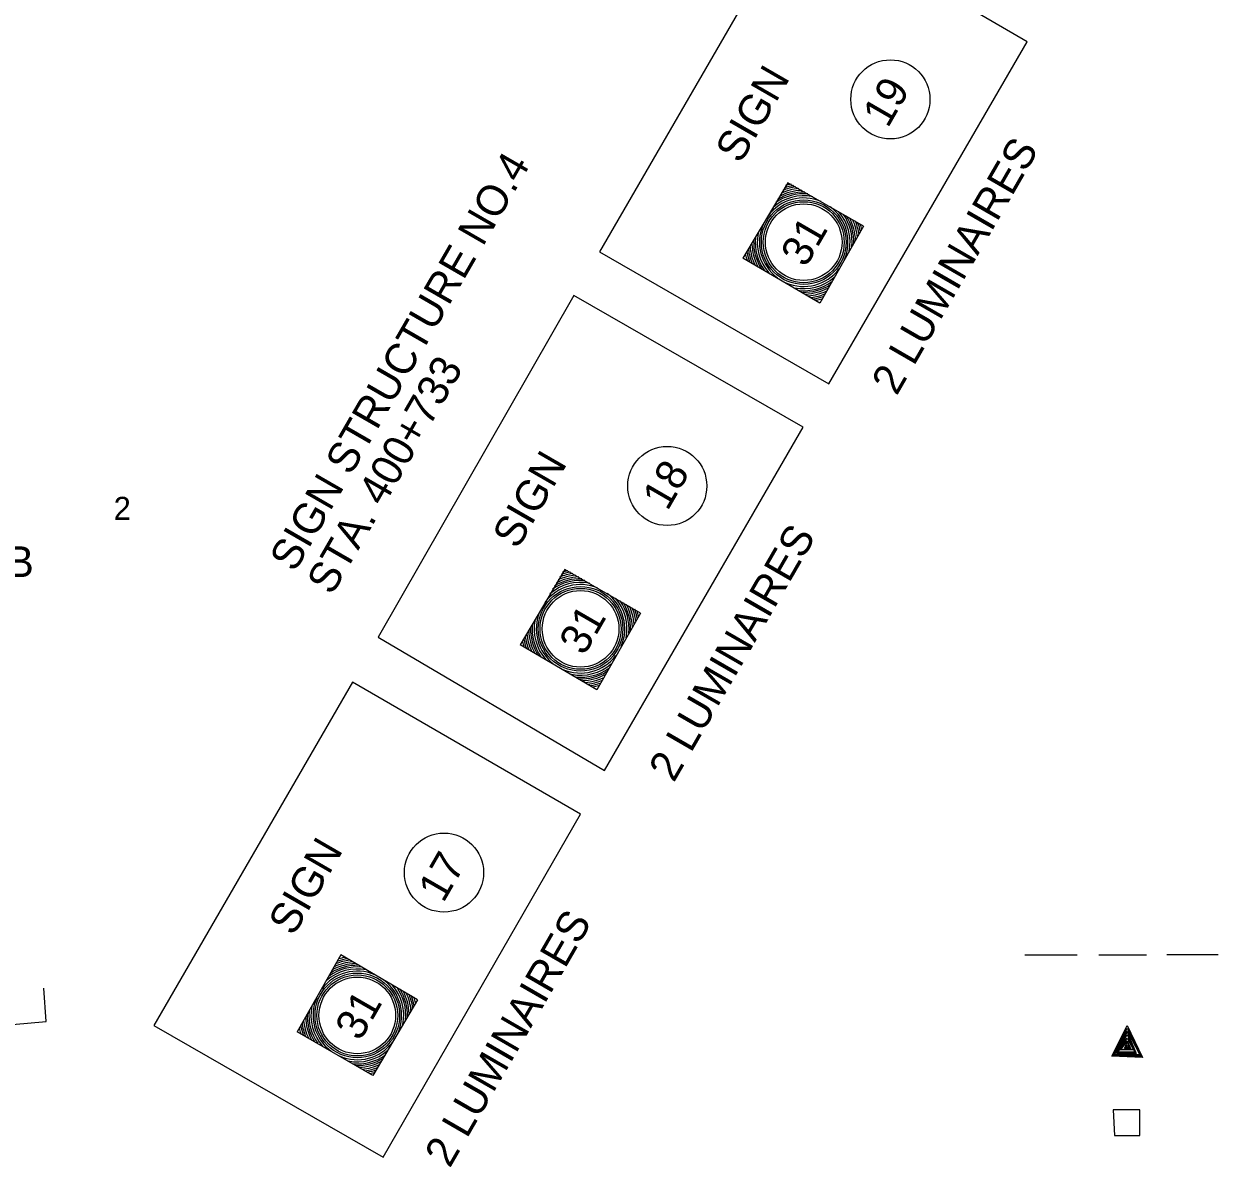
# Model space of a CAD drawing. Extents: x 36 to 2622, y -5330 to 219.
# Drawn here: x 2300.3 to 2416.9, y -4454.9 to -4343.3 of the extents above; entities that cross this region are included whole.
import ezdxf

# ---------------------------------------------------------------- set-up
doc = ezdxf.new("R2010")
doc.units = 0
doc.layers.add('2', color=7, linetype='Continuous')

msp = doc.modelspace()

# ---------------------------------------------------------------- linework, layer by layer
at = {"layer": '2'}
for p, q in [((2397.98, -4434.2), (2403.11, -4434.2)), ((2405.23, -4434.2), (2409.86, -4434.2)), ((2416.86, -4434.2), (2411.86, -4434.2)), ((2302.48, -4440.7), (2302.23, -4437.45)), ((2287.23, -4442.08), (2302.48, -4440.7)), ((2406.48, -4444.08), (2407.98, -4441.08)), ((2406.61, -4444.08), (2407.98, -4441.33)), ((2406.73, -4443.95), (2407.98, -4441.58)), ((2406.98, -4443.83), (2407.98, -4441.7)), ((2407.11, -4443.7), (2407.98, -4441.95)), ((2407.98, -4441.08), (2409.48, -4444.2)), ((2407.98, -4441.33), (2409.36, -4444.08)), ((2407.98, -4441.58), (2409.23, -4443.95)), ((2407.98, -4441.7), (2408.86, -4443.83)), ((2407.98, -4441.95), (2408.73, -4443.7)), ((2407.23, -4443.45), (2407.98, -4442.33)), ((2407.36, -4443.45), (2407.98, -4442.58)), ((2407.73, -4443.33), (2407.98, -4442.7)), ((2407.86, -4443.2), (2407.98, -4442.95)), ((2408.11, -4443.2), (2407.86, -4443.2)), ((2407.98, -4442.33), (2408.61, -4443.45)), ((2407.98, -4442.58), (2408.36, -4443.45)), ((2407.98, -4442.7), (2408.23, -4443.33)), ((2407.98, -4442.95), (2408.11, -4443.2)), ((2409.48, -4444.2), (2406.48, -4444.08)), ((2409.36, -4444.08), (2406.61, -4444.08)), ((2409.23, -4443.95), (2406.73, -4443.95)), ((2408.86, -4443.83), (2406.98, -4443.83)), ((2408.73, -4443.7), (2407.11, -4443.7)), ((2408.61, -4443.45), (2407.23, -4443.45)), ((2408.36, -4443.45), (2407.36, -4443.45)), ((2408.23, -4443.33), (2407.73, -4443.33))]:
    msp.add_line(p, q, dxfattribs=at)
for points in [[(2378.86, -4378.45), (2398.23, -4345.08), (2375.86, -4332.08), (2356.48, -4365.58)], [(2356.98, -4416.2), (2376.36, -4382.7), (2353.98, -4369.83), (2334.86, -4403.2)], [(2335.36, -4453.95), (2354.61, -4420.45), (2332.36, -4407.58), (2312.98, -4441.08)], [(2406.73, -4451.83), (2409.23, -4451.83), (2409.23, -4449.33), (2406.61, -4449.33)]]:
    msp.add_lwpolyline(points, close=True, dxfattribs=at)
for points in [[(2374.86, -4358.83), (2370.48, -4366.2)], [(2382.23, -4363.08), (2374.86, -4358.83)], [(2382.23, -4363.08), (2377.98, -4370.58)], [(2377.98, -4370.58), (2370.48, -4366.2)], [(2353.11, -4396.58), (2348.73, -4403.95)], [(2360.48, -4400.83), (2353.11, -4396.58)], [(2360.48, -4400.83), (2356.23, -4408.33)], [(2356.23, -4408.33), (2348.73, -4403.95)], [(2331.23, -4434.2), (2326.98, -4441.7)], [(2338.73, -4438.58), (2331.23, -4434.2)], [(2338.73, -4438.58), (2334.36, -4445.95)], [(2334.36, -4445.95), (2326.98, -4441.7)]]:
    msp.add_lwpolyline(points, dxfattribs=at)
for centre, radius in [((2384.87, -4350.7), 3.86), ((2376.41, -4364.64), 4.13), ((2376.41, -4364.64), 3.95), ((2376.41, -4364.64), 3.74), ((2363.09, -4388.43), 3.86), ((2354.63, -4402.37), 4.13), ((2354.63, -4402.37), 3.95), ((2354.63, -4402.37), 3.74), ((2341.3, -4426.16), 3.86), ((2332.84, -4440.1), 4.13), ((2332.84, -4440.1), 3.95), ((2332.84, -4440.1), 3.74)]:
    msp.add_circle(centre, radius, dxfattribs=at)
for centre, radius, start, end in [((2376.41, -4364.64), 5.45, 98.0414, 112.0368), ((2376.41, -4364.64), 5.62, 100.231, 109.8414), ((2376.41, -4364.64), 5.8, 102.2801, 107.7872), ((2376.41, -4364.64), 4.32, 66.9038, 143.621), ((2376.41, -4364.64), 4.53, 78.7747, 131.406), ((2376.41, -4364.64), 4.73, 84.969, 125.1626), ((2376.41, -4364.64), 4.89, 88.6036, 121.5088), ((2376.41, -4364.64), 5.06, 92.1022, 117.9954), ((2376.41, -4364.64), 5.26, 95.3377, 114.7487), ((2376.41, -4364.64), 4.32, 336.9038, 53.0962), ((2376.41, -4364.64), 4.53, 348.7747, 41.2253), ((2376.41, -4364.64), 4.73, 354.969, 35.031), ((2376.41, -4364.64), 4.89, 358.6036, 31.3964), ((2376.41, -4364.64), 5.06, 2.1022, 27.8978), ((2376.41, -4364.64), 5.26, 5.3377, 24.6623), ((2376.41, -4364.64), 5.45, 8.0414, 21.9586), ((2376.41, -4364.64), 5.62, 10.231, 19.769), ((2376.41, -4364.64), 4.53, 168.594, 221.406), ((2376.41, -4364.64), 4.32, 156.379, 233.621), ((2376.41, -4364.64), 5.8, 12.2801, 17.7199), ((2376.41, -4364.64), 5.26, 185.2513, 204.7486), ((2376.41, -4364.64), 5.06, 182.0046, 207.9954), ((2376.41, -4364.64), 4.89, 178.4912, 211.5088), ((2376.41, -4364.64), 4.73, 174.8374, 215.1626), ((2376.41, -4364.64), 5.8, 192.2128, 197.7872), ((2376.41, -4364.64), 5.62, 190.1586, 199.8414), ((2376.41, -4364.64), 5.45, 187.9632, 202.0368), ((2376.41, -4364.64), 4.32, 246.379, 323.0962), ((2376.41, -4364.64), 4.53, 258.594, 311.2253), ((2376.41, -4364.64), 4.73, 264.8374, 305.031), ((2376.41, -4364.64), 4.89, 268.4912, 301.3964), ((2376.41, -4364.64), 5.06, 272.0046, 297.8978), ((2376.41, -4364.64), 5.26, 275.2513, 294.6623), ((2376.41, -4364.64), 5.45, 277.9632, 291.9586), ((2376.41, -4364.64), 5.62, 280.1586, 289.769), ((2376.41, -4364.64), 5.8, 282.2128, 287.7199), ((2354.63, -4402.37), 4.73, 84.969, 125.1626), ((2354.63, -4402.37), 4.89, 88.6036, 121.5088), ((2354.63, -4402.37), 5.06, 92.1022, 117.9954), ((2354.63, -4402.37), 5.26, 95.3377, 114.7487), ((2354.63, -4402.37), 5.45, 98.0414, 112.0368), ((2354.63, -4402.37), 5.62, 100.231, 109.8414), ((2354.63, -4402.37), 5.8, 102.2801, 107.7872), ((2354.63, -4402.37), 4.32, 66.9038, 143.621), ((2354.63, -4402.37), 4.53, 78.7747, 131.406), ((2354.63, -4402.37), 4.32, 336.9038, 53.0962), ((2354.63, -4402.37), 4.53, 348.7747, 41.2253), ((2354.63, -4402.37), 4.73, 354.969, 35.031), ((2354.63, -4402.37), 4.89, 358.6036, 31.3964), ((2354.63, -4402.37), 5.06, 2.1022, 27.8978), ((2354.63, -4402.37), 4.32, 156.379, 233.621), ((2354.63, -4402.37), 5.26, 5.3377, 24.6623), ((2354.63, -4402.37), 5.45, 8.0414, 21.9586), ((2354.63, -4402.37), 5.62, 10.231, 19.769), ((2354.63, -4402.37), 5.8, 12.2801, 17.7199), ((2354.63, -4402.37), 4.89, 178.4912, 211.5088), ((2354.63, -4402.37), 4.73, 174.8374, 215.1626), ((2354.63, -4402.37), 4.53, 168.594, 221.406), ((2354.63, -4402.37), 5.8, 192.2128, 197.7872), ((2354.63, -4402.37), 5.62, 190.1586, 199.8414), ((2354.63, -4402.37), 5.45, 187.9632, 202.0368), ((2354.63, -4402.37), 5.26, 185.2513, 204.7486), ((2354.63, -4402.37), 5.06, 182.0046, 207.9954), ((2354.63, -4402.37), 4.32, 246.379, 323.0962), ((2354.63, -4402.37), 4.53, 258.594, 311.2253), ((2354.63, -4402.37), 4.73, 264.8374, 305.031), ((2354.63, -4402.37), 4.89, 268.4912, 301.3964), ((2354.63, -4402.37), 5.06, 272.0046, 297.8978), ((2354.63, -4402.37), 5.26, 275.2513, 294.6623), ((2354.63, -4402.37), 5.45, 277.9632, 291.9586), ((2354.63, -4402.37), 5.62, 280.1586, 289.769), ((2354.63, -4402.37), 5.8, 282.2128, 287.7199), ((2332.84, -4440.1), 5.06, 92.1022, 117.9954), ((2332.84, -4440.1), 5.26, 95.3377, 114.7487), ((2332.84, -4440.1), 5.45, 98.0414, 112.0368), ((2332.84, -4440.1), 5.62, 100.231, 109.8414), ((2332.84, -4440.1), 5.8, 102.2801, 107.7872), ((2332.84, -4440.1), 4.32, 66.9038, 143.621), ((2332.84, -4440.1), 4.53, 78.7747, 131.406), ((2332.84, -4440.1), 4.73, 84.969, 125.1626), ((2332.84, -4440.1), 4.89, 88.6036, 121.5088), ((2332.84, -4440.1), 4.32, 336.9038, 53.0962), ((2332.84, -4440.1), 4.53, 348.7747, 41.2253), ((2332.84, -4440.1), 4.73, 354.969, 35.031), ((2332.84, -4440.1), 4.32, 156.379, 233.621), ((2332.84, -4440.1), 4.89, 358.6036, 31.3964), ((2332.84, -4440.1), 5.06, 2.1022, 27.8978), ((2332.84, -4440.1), 5.26, 5.3377, 24.6623), ((2332.84, -4440.1), 5.45, 8.0414, 21.9586), ((2332.84, -4440.1), 5.62, 10.231, 19.769), ((2332.84, -4440.1), 5.8, 12.2801, 17.7199), ((2332.84, -4440.1), 4.73, 174.8374, 215.1626), ((2332.84, -4440.1), 4.53, 168.594, 221.406), ((2332.84, -4440.1), 5.45, 187.9632, 202.0368), ((2332.84, -4440.1), 5.26, 185.2513, 204.7486), ((2332.84, -4440.1), 5.06, 182.0046, 207.9954), ((2332.84, -4440.1), 4.89, 178.4912, 211.5088), ((2332.84, -4440.1), 5.8, 192.2128, 197.7872), ((2332.84, -4440.1), 5.62, 190.1586, 199.8414), ((2332.84, -4440.1), 4.32, 246.379, 323.0962), ((2332.84, -4440.1), 4.53, 258.594, 311.2253), ((2332.84, -4440.1), 4.73, 264.8374, 305.031), ((2332.84, -4440.1), 4.89, 268.4912, 301.3964), ((2332.84, -4440.1), 5.06, 272.0046, 297.8978), ((2332.84, -4440.1), 5.26, 275.2513, 294.6623), ((2332.84, -4440.1), 5.45, 277.9632, 291.9586), ((2332.84, -4440.1), 5.62, 280.1586, 289.769), ((2332.84, -4440.1), 5.8, 282.2128, 287.7199)]:
    msp.add_arc(centre, radius, start, end, dxfattribs=at)

# ---------------------------------------------------------------- texts
for s, height, rotation, p in [('SIGN', 2.996, 60, (2370.23, -4357.08)), ('19', 2.996, 60, (2384.61, -4353.58)), ('2 LUMINAIRES', 2.9955, 60, (2385.48, -4379.7)), ('SIGN STRUCTURE NO.4', 2.9955, 60, (2326.73, -4396.95)), ('31', 2.996, 60, (2376.61, -4367.2)), ('STA. 400+733', 2.9955, 60, (2330.36, -4399.2)), ('SIGN', 2.996, 60, (2348.48, -4394.7)), ('18', 2.996, 60, (2363.11, -4390.95)), ('2', 2.25, 0.0055, (2309.06, -4391.74)), ('2 LUMINAIRES', 2.9955, 60, (2363.73, -4417.45)), ('CIRCUIT B', 2.996, 360, (2281.23, -4397.32)), ('31', 2.996, 60, (2354.98, -4405.08)), ('SIGN', 2.996, 60, (2326.61, -4432.45)), ('17', 2.996, 60, (2341.23, -4429.2)), ('2 LUMINAIRES', 2.9955, 60, (2341.86, -4455.08)), ('31', 2.996, 60, (2333.11, -4442.7))]:
    msp.add_text(s, height=height, rotation=rotation, dxfattribs=at).set_placement(p)

doc.saveas('drawing.dxf')
